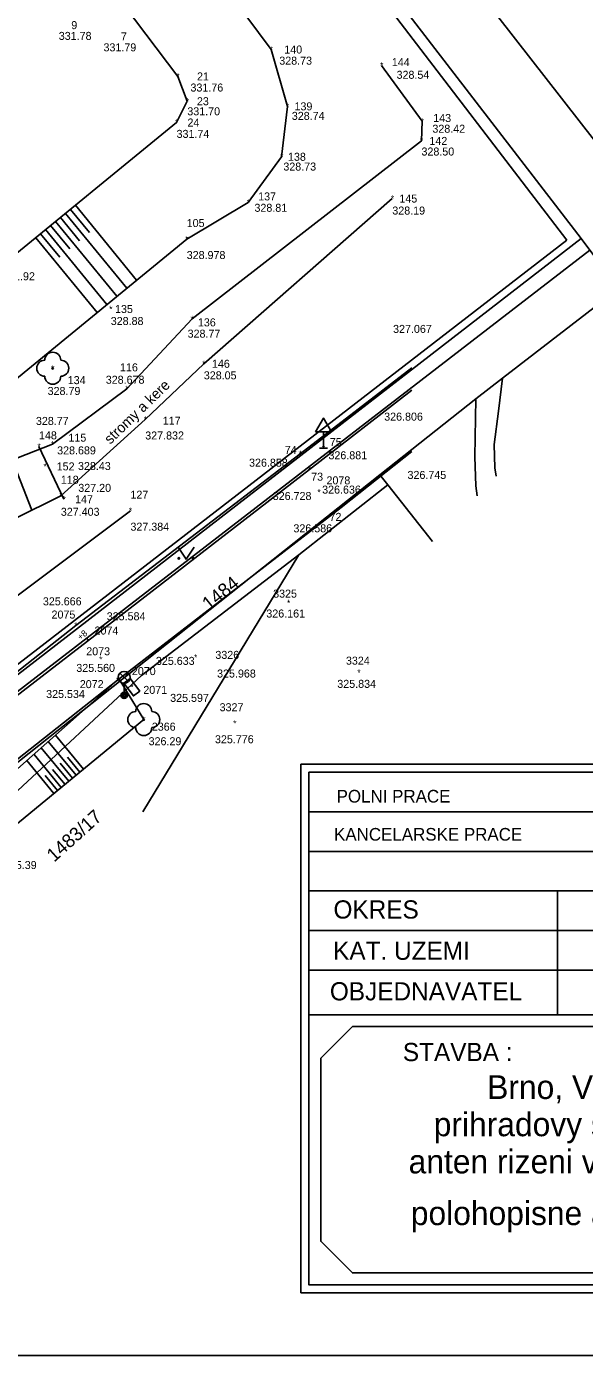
# Model space of a CAD drawing. Extents: x -600587 to -600377, y -1159886 to -1159708.
# Drawn here: x -600482.7 to -600447.8, y -1159886.4 to -1159803.3 of the extents above; entities that cross this region are included whole.
import ezdxf

# ---------------------------------------------------------------- set-up
doc = ezdxf.new("R2010")
doc.units = 0
for name, color, linetype in [('Hranice parcel', 7, 'Continuous'), ('Level 24', 7, 'Continuous'), ('Level 33', 7, 'Continuous'), ('Level 34', 7, 'Continuous'), ('Parcelní čísla', 7, 'Continuous'), ('Vnitřní kresba', 7, 'Continuous'), ('Vrstva 11', 7, 'Continuous'), ('Vrstva 14', 7, 'Continuous'), ('Vrstva 16', 7, 'Continuous'), ('Vrstva 2', 7, 'Continuous'), ('Vrstva 22', 7, 'Continuous'), ('Vrstva 36', 7, 'Continuous'), ('Vrstva 40', 7, 'Continuous'), ('Vrstva 58', 7, 'Continuous'), ('Vrstva 59', 7, 'Continuous'), ('Vrstva 60', 7, 'Continuous'), ('Vrstva 63', 7, 'Continuous'), ('Vrstva 7', 7, 'Continuous')]:
    doc.layers.add(name, color=color, linetype=linetype)

msp = doc.modelspace()

# ---------------------------------------------------------------- linework, layer by layer
at = {"layer": 'Hranice parcel'}
for p, q in [((-600448.05, -1159816.59), (-600488.61, -1159847.98)), ((-600454.69, -1159830.23), (-600454.62, -1159826.61)), ((-600460.12, -1159831.97), (-600465.68, -1159836.35)), ((-600457.324, -1159835.521), (-600460.12, -1159831.97))]:
    msp.add_line(p, q, dxfattribs=at)
for points in [[(-600530.91, -1159710.13), (-600493.42, -1159757.63), (-600491.23, -1159760.48), (-600448.05, -1159816.59)], [(-600448.05, -1159816.59), (-600447.51, -1159817.31), (-600445.7, -1159819.7)], [(-600454.62, -1159826.61), (-600452.97, -1159825.3), (-600445.7, -1159819.7)], [(-600460.12, -1159831.97), (-600460.61, -1159831.35), (-600454.62, -1159826.61)], [(-600454.537, -1159832.65), (-600454.63, -1159832.03), (-600454.69, -1159830.23)], [(-600465.68, -1159836.35), (-600475.51, -1159843.89), (-600483.51, -1159851.34), (-600488.17, -1159855.96)], [(-600465.68, -1159836.35), (-600475.425, -1159852.393)]]:
    msp.add_lwpolyline(points, dxfattribs=at)
at = {"layer": 'Level 24'}
msp.add_lwpolyline([(-600476.607, -1159844.361), (-600476.005, -1159845.159), (-600475.606, -1159844.858), (-600476.208, -1159844.06)], close=True, dxfattribs=at)
at = {"layer": 'Level 33'}
for p, q in [((-600476.847, -1159844.264), (-600476.317, -1159843.734)), ((-600476.847, -1159843.734), (-600476.317, -1159844.264)), ((-600476.582, -1159844.374), (-600476.582, -1159845.124))]:
    msp.add_line(p, q, dxfattribs=at)
for centre, radius in [((-600476.582, -1159843.999), 0.375), ((-600476.582, -1159845.124), 0.2), ((-600476.582, -1159845.124), 0.145), ((-600476.582, -1159845.124), 0.0876)]:
    msp.add_circle(centre, radius, dxfattribs=at)
at = {"layer": 'Level 34'}
for p, q in [((-600464.144, -1159828.669), (-600464.144, -1159829.687)), ((-600464.394, -1159829.687), (-600463.894, -1159829.687))]:
    msp.add_line(p, q, dxfattribs=at)
msp.add_lwpolyline([(-600464.644, -1159828.669), (-600463.644, -1159828.669), (-600464.144, -1159827.803)], close=True, dxfattribs=at)
at = {"layer": 'Vnitřní kresba'}
for p, q in [((-600494.19, -1159750.03), (-600447.22, -1159810.47)), ((-600491.69, -1159760.84), (-600448.94, -1159816.68)), ((-600448.94, -1159816.68), (-600488.87, -1159847.53)), ((-600447.51, -1159817.31), (-600489.24, -1159849.51)), ((-600452.97, -1159825.3), (-600453.22, -1159827.38)), ((-600453.22, -1159827.38), (-600453.48, -1159829.46)), ((-600453.48, -1159829.46), (-600453.45, -1159830.9)), ((-600453.45, -1159830.9), (-600453.351, -1159831.428)), ((-600489.18, -1159854.01), (-600460.61, -1159831.35))]:
    msp.add_line(p, q, dxfattribs=at)
at = {"layer": 'Vrstva 11'}
for p, q in [((-600480.248, -1159815.016), (-600476.422, -1159819.687)), ((-600479.938, -1159814.763), (-600478.744, -1159816.22)), ((-600479.629, -1159814.51), (-600475.803, -1159819.18)), ((-600481.486, -1159816.03), (-600477.659, -1159820.701)), ((-600481.177, -1159815.776), (-600479.982, -1159817.234)), ((-600480.867, -1159815.523), (-600477.04, -1159820.194)), ((-600480.557, -1159815.27), (-600479.363, -1159816.727)), ((-600482.105, -1159816.536), (-600478.278, -1159821.208)), ((-600481.796, -1159816.283), (-600480.601, -1159817.741)), ((-600482.355, -1159833.554), (-600483.574, -1159830.42)), ((-600465.02, -1159831.014), (-600478.865, -1159841.734)), ((-600463.025, -1159833.392), (-600476.997, -1159844.167)), ((-600484.84, -1159840.063), (-600476.191, -1159833.587)), ((-600478.865, -1159841.734), (-600486.956, -1159847.971)), ((-600476.997, -1159844.167), (-600485.703, -1159851.054))]:
    msp.add_line(p, q, dxfattribs=at)
for points in [[(-600472.677, -1159816.619), (-600468.83, -1159814.33), (-600466.75, -1159811.48), (-600466.39, -1159808.33), (-600467.41, -1159804.78), (-600472.015, -1159798.548)], [(-600476.58, -1159802.04), (-600473.23, -1159806.46), (-600472.64, -1159808.01), (-600473.31, -1159809.34), (-600484.2, -1159818.25)], [(-600476.419, -1159825.97), (-600472.34, -1159821.61), (-600458.02, -1159810.49), (-600457.98, -1159809.26), (-600460.51, -1159805.77)], [(-600459.84, -1159814.09), (-600471.61, -1159824.41), (-600475.267, -1159827.89)], [(-600472.677, -1159816.619), (-600485.977, -1159827.515), (-600490.548, -1159828.224), (-600493.772, -1159826.17), (-600497.07, -1159821.79)], [(-600502.87, -1159824.07), (-600498.564, -1159829.569), (-600492.522, -1159832.403), (-600487.072, -1159831.78), (-600481.048, -1159829.438), (-600476.419, -1159825.97)], [(-600465.02, -1159831.014), (-600458.629, -1159826.063)], [(-600475.267, -1159827.89), (-600480.537, -1159832.655), (-600489.284, -1159836.98), (-600495.817, -1159836.239), (-600499.585, -1159834.387), (-600502.72, -1159834.41)], [(-600458.629, -1159829.892), (-600463.025, -1159833.392)]]:
    msp.add_lwpolyline(points, dxfattribs=at)
at = {"layer": 'Vrstva 14'}
for p, q in [((-600481.9, -1159829.57), (-600480.34, -1159832.87)), ((-600487.621, -1159853.594), (-600476.997, -1159844.167)), ((-600476.957, -1159843.999), (-600475.361, -1159846.637)), ((-600475.361, -1159846.637), (-600485.697, -1159855.144)), ((-600481.766, -1159848.399), (-600480.044, -1159850.491)), ((-600481.317, -1159848), (-600479.58, -1159850.11)), ((-600480.868, -1159847.602), (-600479.117, -1159849.728)), ((-600482.664, -1159849.196), (-600480.97, -1159851.254)), ((-600482.201, -1159848.814), (-600480.507, -1159850.872)), ((-600480.12, -1159848.982), (-600479.349, -1159849.919)), ((-600481.046, -1159849.745), (-600480.275, -1159850.682)), ((-600480.583, -1159849.363), (-600479.812, -1159850.3)), ((-600481.51, -1159850.126), (-600480.738, -1159851.063))]:
    msp.add_line(p, q, dxfattribs=at)
at = {"layer": 'Vrstva 2'}
msp.add_lwpolyline([(-600586.635, -1159886.355), (-600376.635, -1159886.355), (-600376.635, -1159737.855), (-600586.635, -1159737.855)], close=True, dxfattribs=at)
at = {"layer": 'Vrstva 22'}
for centre in [(-600481.04, -1159824.69), (-600475.361, -1159846.637)]:
    msp.add_circle(centre, 0.05, dxfattribs=at)
for centre, start, end in [((-600481.54, -1159824.69), 90, 270), ((-600481.04, -1159824.19), 0, 180), ((-600480.54, -1159824.69), 270, 90), ((-600481.04, -1159825.19), 180, 0), ((-600475.361, -1159846.137), 0, 180), ((-600475.861, -1159846.637), 90, 270), ((-600474.861, -1159846.637), 270, 90), ((-600475.361, -1159847.137), 180, 0)]:
    msp.add_arc(centre, 0.5, start, end, dxfattribs=at)
at = {"layer": 'Vrstva 36'}
msp.add_lwpolyline([(-600473.22, -1159835.869), (-600472.72, -1159836.619), (-600472.22, -1159835.869)], dxfattribs=at)
for centre in [(-600473.17, -1159836.569), (-600472.27, -1159836.569)]:
    msp.add_circle(centre, 0.05, dxfattribs=at)
at = {"layer": 'Vrstva 63'}
msp.add_line((-600449.53, -1159865.075), (-600449.53, -1159857.341), dxfattribs=at)
for points in [[(-600380.469, -1159849.427), (-600465.544, -1159849.427), (-600465.544, -1159882.442), (-600380.469, -1159882.442), (-600380.469, -1159849.427)], [(-600380.963, -1159849.921), (-600465.049, -1159849.921), (-600465.049, -1159881.947), (-600380.963, -1159881.947), (-600380.963, -1159849.921)], [(-600465.049, -1159852.395), (-600416.131, -1159852.395)], [(-600465.049, -1159854.868), (-600416.131, -1159854.868)], [(-600465.049, -1159857.341), (-600416.131, -1159857.341)], [(-600465.049, -1159859.814), (-600416.131, -1159859.814)], [(-600465.049, -1159862.287), (-600416.131, -1159862.287)], [(-600465.049, -1159865.075), (-600416.131, -1159865.075)]]:
    msp.add_lwpolyline(points, dxfattribs=at)
msp.add_lwpolyline([(-600464.307, -1159867.795), (-600462.329, -1159865.817), (-600418.851, -1159865.817), (-600416.873, -1159867.795), (-600416.873, -1159879.227), (-600418.851, -1159881.205), (-600462.329, -1159881.205), (-600464.307, -1159879.227)], close=True, dxfattribs=at)
at = {"layer": 'Vrstva 7'}
for p, q in [((-600465.594, -1159830.035), (-600458.629, -1159824.656)), ((-600479.599, -1159840.769), (-600465.594, -1159830.035)), ((-600487.783, -1159847.211), (-600479.599, -1159840.769))]:
    msp.add_line(p, q, dxfattribs=at)

# ---------------------------------------------------------------- texts
at = {"layer": 'Parcelní čísla'}
for s, rotation, p in [('1484', 39, (-600471.284, -1159839.861)), ('1483/17', 42, (-600480.95, -1159855.575))]:
    msp.add_text(s, height=0.85, rotation=rotation, dxfattribs=at).set_placement(p)
at = {"layer": 'Vrstva 16'}
msp.add_text('+8', height=0.4, rotation=38.75561, dxfattribs=at).set_placement((-600479.311, -1159841.697))
at = {"layer": 'Vrstva 40'}
msp.add_text('stromy a kere', height=0.65, rotation=44.10014, dxfattribs=at).set_placement((-600477.45, -1159829.475))
at = {"layer": 'Vrstva 58'}
for s, p in [('331.78', (-600480.665, -1159804.179)), ('331.79', (-600477.872, -1159804.894)), ('328.73', (-600466.898, -1159805.725)), ('331.76', (-600472.442, -1159807.405)), ('328.54', (-600459.575, -1159806.608)), ('331.70', (-600472.64, -1159808.889)), ('328.74', (-600466.115, -1159809.176)), ('331.74', (-600473.31, -1159810.299)), ('328.42', (-600457.339, -1159809.978)), ('328.50', (-600458.02, -1159811.402)), ('328.73', (-600466.643, -1159812.341)), ('328.81', (-600468.448, -1159814.916)), ('328.19', (-600459.84, -1159815.089)), ('328.978', (-600472.677, -1159817.869)), ('331.92', (-600484.2, -1159819.193)), ('328.88', (-600477.42, -1159821.989)), ('328.77', (-600472.621, -1159822.778)), ('327.067', (-600459.792, -1159822.483)), ('328.678', (-600477.731, -1159825.658)), ('328.05', (-600471.61, -1159825.382)), ('328.79', (-600481.361, -1159826.358)), ('326.806', (-600460.348, -1159827.962)), ('328.77', (-600482.091, -1159828.23)), ('327.832', (-600475.267, -1159829.14)), ('328.689', (-600480.766, -1159830.07)), ('326.881', (-600463.828, -1159830.375)), ('328.43', (-600479.466, -1159831.047)), ('326.858', (-600468.785, -1159830.838)), ('326.745', (-600458.891, -1159831.604)), ('327.20', (-600479.445, -1159832.411)), ('326.728', (-600467.306, -1159832.918)), ('326.636', (-600464.221, -1159832.52)), ('327.403', (-600480.537, -1159833.905)), ('327.384', (-600476.191, -1159834.837)), ('326.586', (-600466.015, -1159834.938)), ('325.666', (-600481.657, -1159839.5)), ('325.584', (-600477.67, -1159840.432)), ('326.161', (-600467.706, -1159840.261)), ('325.560', (-600479.571, -1159843.659)), ('325.633', (-600474.6, -1159843.219)), ('325.968', (-600470.78, -1159844.01)), ('325.834', (-600463.275, -1159844.654)), ('325.534', (-600481.453, -1159845.288)), ('325.597', (-600473.709, -1159845.53)), ('326.29', (-600475.056, -1159848.239)), ('325.776', (-600470.913, -1159848.115)), ('325.39', (-600484.091, -1159855.972))]:
    msp.add_text(s, height=0.5, dxfattribs=at).set_placement(p)
at = {"layer": 'Vrstva 59'}
for s, p in [('9', (-600479.883, -1159803.507)), ('7', (-600476.788, -1159804.216)), ('140', (-600466.585, -1159805.03)), ('144', (-600459.869, -1159805.819)), ('21', (-600472.034, -1159806.71)), ('23', (-600472.039, -1159808.26)), ('139', (-600465.947, -1159808.58)), ('24', (-600472.628, -1159809.59)), ('143', (-600457.285, -1159809.309)), ('142', (-600457.526, -1159810.74)), ('138', (-600466.353, -1159811.73)), ('137', (-600468.217, -1159814.206)), ('145', (-600459.399, -1159814.34)), ('105', (-600472.677, -1159815.869)), ('135', (-600477.153, -1159821.24)), ('136', (-600471.979, -1159822.074)), ('146', (-600471.102, -1159824.66)), ('134', (-600480.105, -1159825.682)), ('116', (-600476.842, -1159824.884)), ('117', (-600474.172, -1159828.214)), ('148', (-600481.9, -1159829.132)), ('115', (-600480.061, -1159829.274)), ('75', (-600463.746, -1159829.55)), ('74', (-600466.553, -1159830.041)), ('152', (-600480.795, -1159831.07)), ('118', (-600480.537, -1159831.905)), ('73', (-600464.908, -1159831.714)), ('2078', (-600463.951, -1159831.943)), ('147', (-600479.645, -1159833.12)), ('127', (-600476.191, -1159832.837)), ('72', (-600463.76, -1159834.225)), ('3325', (-600467.281, -1159839.018)), ('2075', (-600481.116, -1159840.325)), ('2074', (-600478.431, -1159841.324)), ('2073', (-600478.95, -1159842.62)), ('3326', (-600470.889, -1159842.845)), ('2070', (-600476.101, -1159843.857)), ('3324', (-600462.736, -1159843.204)), ('2072', (-600479.354, -1159844.672)), ('2071', (-600475.386, -1159845.031)), ('3327', (-600470.623, -1159846.115)), ('2366', (-600474.857, -1159847.329))]:
    msp.add_text(s, height=0.5, dxfattribs=at).set_placement(p)
at = {"layer": 'Vrstva 60'}
for p in [(-600467.508, -1159804.98), (-600460.608, -1159805.97), (-600473.328, -1159806.66), (-600472.738, -1159808.21), (-600466.488, -1159808.53), (-600473.408, -1159809.54), (-600458.078, -1159809.46), (-600458.118, -1159810.69), (-600466.848, -1159811.68), (-600468.928, -1159814.53), (-600459.938, -1159814.29), (-600472.775, -1159816.819), (-600477.518, -1159821.19), (-600472.438, -1159821.81), (-600471.708, -1159824.61), (-600481.138, -1159824.89), (-600476.517, -1159826.17), (-600475.365, -1159828.09), (-600481.146, -1159829.638), (-600481.998, -1159829.77), (-600465.692, -1159830.235), (-600464.242, -1159829.887), (-600481.618, -1159831.02), (-600465.118, -1159831.214), (-600480.635, -1159832.855), (-600464.519, -1159832.634), (-600480.438, -1159833.07), (-600476.289, -1159833.787), (-600463.123, -1159833.592), (-600466.416, -1159839.553), (-600479.697, -1159840.969), (-600478.963, -1159841.934), (-600472.22, -1159842.96), (-600478.145, -1159843.066), (-600477.095, -1159844.367), (-600462.026, -1159843.905), (-600476.68, -1159845.324), (-600476.199, -1159844.807), (-600475.459, -1159846.837), (-600469.778, -1159847.065)]:
    msp.add_text('*', height=0.4, dxfattribs=at).set_placement(p)
at = {"layer": 'Vrstva 63'}
for s, height, p in [('POLNI PRACE', 0.79041, (-600463.318, -1159851.819)), ('KANCELARSKE PRACE ', 0.79041, (-600463.478, -1159854.198)), ('OKRES ', 1.1376, (-600463.514, -1159859.066)), ('KAT. UZEMI', 1.1376, (-600463.536, -1159861.642)), ('OBJEDNAVATEL ', 1.13763, (-600463.739, -1159864.177)), ('STAVBA :', 1.1376, (-600459.182, -1159867.971)), ('Brno, VDJ+ATS Barvicova – ', 1.48387, (-600453.919, -1159870.336)), ('prihradovy stozar pro umisteni ', 1.48387, (-600457.256, -1159872.661)), ('anten rizeni vodarenskych objektu', 1.48387, (-600458.822, -1159874.986)), ('polohopisne a vyskopisne zamereni', 1.48387, (-600458.686, -1159878.214))]:
    msp.add_text(s, height=height, dxfattribs=at).set_placement(p)

doc.saveas('drawing.dxf')
